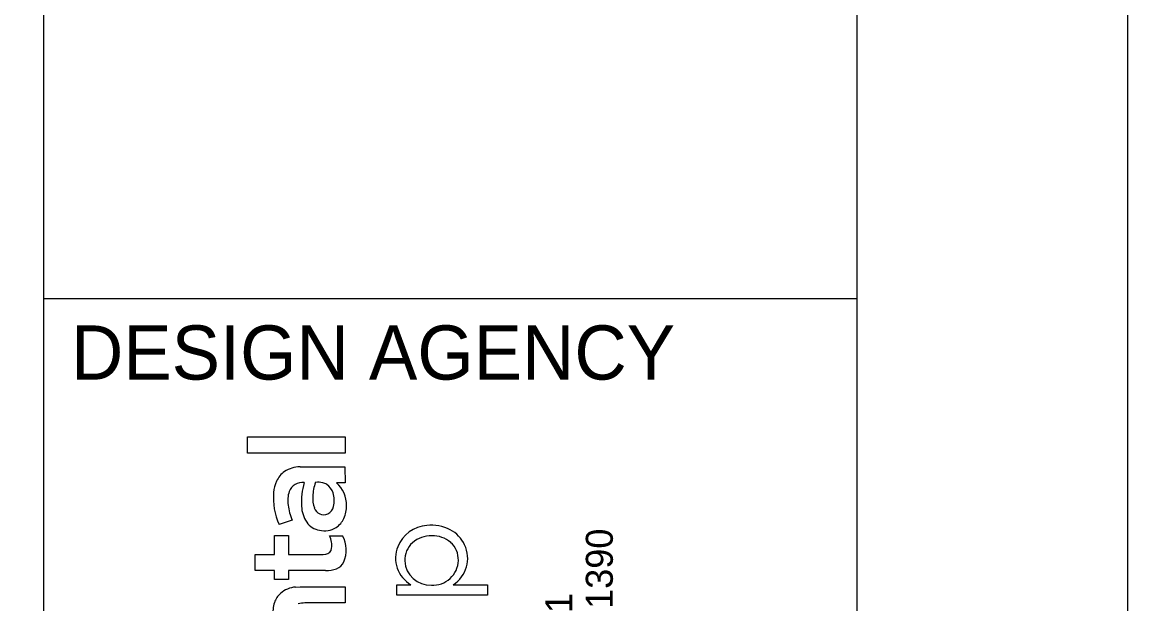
# Model space of a CAD drawing. Extents: x 0 to 34, y 0 to 22.
# Drawn here: x 31.96 to 34, y 4.436 to 5.51 of the extents above; entities that cross this region are included whole.
import ezdxf

# ---------------------------------------------------------------- set-up
doc = ezdxf.new("R2010")
doc.units = 0
for name, color, linetype in [('SH_Border', 7, 'Continuous'), ('SH_Cut_Line', 7, 'Continuous'), ('SH_Data', 7, 'Continuous')]:
    doc.layers.add(name, color=color, linetype=linetype)

msp = doc.modelspace()

# ---------------------------------------------------------------- linework, layer by layer
at = {"layer": 'SH_Border'}
for p, q in [((32, 0.5), (32, 21.5)), ((32, 5), (33.5, 5))]:
    msp.add_line(p, q, dxfattribs=at)
msp.add_lwpolyline([(1.5, 21.5), (33.5, 21.5), (33.5, 0.5), (1.5, 0.5)], close=True, dxfattribs=at)
at = {"layer": 'SH_Cut_Line'}
msp.add_lwpolyline([(0, 0), (34, 0), (34, 22), (0, 22)], close=True, dxfattribs=at)
at = {"layer": 'SH_Data'}
for p, q in [((32.3756, 4.7141), (32.3756, 4.744)), ((32.3756, 4.744), (32.5557, 4.744)), ((32.5557, 4.744), (32.5557, 4.7141)), ((32.5557, 4.7141), (32.3756, 4.7141)), ((32.4727, 4.689), (32.5555, 4.6892)), ((32.5555, 4.6892), (32.5557, 4.6596)), ((32.5557, 4.6596), (32.5397, 4.6596)), ((32.4582, 4.5904), (32.4343, 4.5823)), ((32.4254, 4.527), (32.4255, 4.5621)), ((32.4255, 4.5621), (32.4511, 4.5621)), ((32.4511, 4.5621), (32.4512, 4.527)), ((32.527, 4.5616), (32.5511, 4.5616)), ((32.3896, 4.4972), (32.3896, 4.527)), ((32.3896, 4.527), (32.4254, 4.527)), ((32.4512, 4.527), (32.515, 4.527)), ((32.515, 4.527), (32.52, 4.5275)), ((32.4254, 4.4972), (32.3896, 4.4972)), ((32.4254, 4.4807), (32.4254, 4.4972)), ((32.5197, 4.4972), (32.4511, 4.4972)), ((32.4511, 4.4972), (32.4511, 4.4807)), ((32.4511, 4.4807), (32.4254, 4.4807)), ((32.6515, 4.4521), (32.6515, 4.4711)), ((32.6515, 4.4711), (32.6771, 4.4711)), ((32.7549, 4.4713), (32.8186, 4.4711)), ((32.8186, 4.4711), (32.8184, 4.4521)), ((32.4644, 4.4669), (32.4729, 4.4673)), ((32.4729, 4.4673), (32.5557, 4.4673)), ((32.5557, 4.4673), (32.5557, 4.4375)), ((32.8184, 4.4521), (32.6515, 4.4521)), ((32.5557, 4.4375), (32.4814, 4.4375))]:
    msp.add_line(p, q, dxfattribs=at)
msp.add_lwpolyline([(32.3756, 4.7141), (32.3756, 4.744), (32.5557, 4.744), (32.5557, 4.7141)], close=True, dxfattribs=at)
for points in [[(32.4727, 4.689), (32.5555, 4.6892), (32.5557, 4.6596)], [(32.5557, 4.6596), (32.5397, 4.6596)], [(32.4582, 4.5904), (32.4343, 4.5823)], [(32.5197, 4.4972), (32.4511, 4.4972), (32.4511, 4.4807), (32.4254, 4.4807), (32.4254, 4.4972), (32.3896, 4.4972), (32.3896, 4.527), (32.4254, 4.527), (32.4255, 4.5621), (32.4511, 4.5621), (32.4512, 4.527), (32.515, 4.527), (32.52, 4.5275)], [(32.527, 4.5616), (32.5511, 4.5616)], [(32.7549, 4.4713), (32.8186, 4.4711), (32.8184, 4.4521), (32.6515, 4.4521)], [(32.6515, 4.4521), (32.6515, 4.4711), (32.6771, 4.4711)], [(32.4644, 4.4669), (32.4729, 4.4673), (32.5557, 4.4673), (32.5557, 4.4375), (32.4814, 4.4375)]]:
    msp.add_lwpolyline(points, dxfattribs=at)
for centre, radius, start, end in [((32.4685, 4.6447), 0.043, 124.537, 155.6594), ((32.4685, 4.6447), 0.043, 124.537, 155.6594), ((32.4745, 4.6326), 0.0565, 91.8942, 122.6317), ((32.4745, 4.6326), 0.0565, 91.8942, 122.6317), ((32.4882, 4.6361), 0.0646, 155.9764, 175.3149), ((32.4882, 4.6361), 0.0646, 155.9764, 175.3149), ((32.4753, 4.6356), 0.024, 119.4252, 161.6629), ((32.4753, 4.6356), 0.024, 119.4252, 161.6629), ((32.4779, 4.6278), 0.0321, 85.3802, 116.6222), ((32.4779, 4.6278), 0.0321, 85.3802, 116.6222), ((32.5879, 4.6251), 0.1129, 162.0821, 184.5285), ((32.5879, 4.6251), 0.1129, 162.0821, 184.5285), ((32.5801, 4.6313), 0.0841, 159.8366, 178.0362), ((32.5801, 4.6313), 0.0841, 159.8366, 178.0362), ((32.5051, 4.6074), 0.053, 79.6696, 94.2322), ((32.5051, 4.6074), 0.053, 79.6696, 94.2322), ((32.5089, 4.6364), 0.0238, 56.8913, 76.2149), ((32.5089, 4.6364), 0.0238, 56.8913, 76.2149), ((32.5052, 4.6318), 0.0297, 17.5984, 55.7282), ((32.5052, 4.6318), 0.0297, 17.5984, 55.7282), ((32.5055, 4.6191), 0.0529, 358.0746, 49.762), ((32.5055, 4.6191), 0.0529, 358.0746, 49.762), ((32.5364, 4.6308), 0.113, 174.6101, 205.3899), ((32.5364, 4.6308), 0.113, 174.6101, 205.3899), ((32.5076, 4.6265), 0.0576, 163.1369, 188.1675), ((32.5076, 4.6265), 0.0576, 163.1369, 188.1675), ((32.5466, 4.6303), 0.0506, 175.5903, 199.8857), ((32.5466, 4.6303), 0.0506, 175.5903, 199.8857), ((32.4916, 4.6264), 0.0443, 345.9408, 18.9919), ((32.4916, 4.6264), 0.0443, 345.9408, 18.9919), ((32.5473, 4.6297), 0.0973, 186.7598, 203.7981), ((32.5473, 4.6297), 0.0973, 186.7598, 203.7981), ((32.5328, 4.6187), 0.0575, 182.5676, 213.7144), ((32.5328, 4.6187), 0.0575, 182.5676, 213.7144), ((32.5164, 4.6189), 0.0184, 198.2844, 293.3081), ((32.5164, 4.6189), 0.0184, 198.2844, 293.3081), ((32.5152, 4.6199), 0.0199, 295.2883, 347.4639), ((32.5152, 4.6199), 0.0199, 295.2883, 347.4639), ((32.5019, 4.6168), 0.0566, 336.016, 0.5951), ((32.5019, 4.6168), 0.0566, 336.016, 0.5951), ((32.5175, 4.6097), 0.0394, 303.4436, 336.18), ((32.5175, 4.6097), 0.0394, 303.4436, 336.18), ((32.5149, 4.6078), 0.0366, 215.0668, 259.8133), ((32.5149, 4.6078), 0.0366, 215.0668, 259.8133), ((32.5175, 4.6131), 0.0423, 257.5256, 300.882), ((32.5175, 4.6131), 0.0423, 257.5256, 300.882), ((32.7108, 4.5182), 0.0624, 93.9866, 158.3119), ((32.7108, 4.5182), 0.0624, 93.9866, 158.3119), ((32.7156, 4.5065), 0.0746, 62.6889, 97.0135), ((32.7156, 4.5065), 0.0746, 62.6889, 97.0135), ((32.7212, 4.5191), 0.0608, 25.0657, 61.9602), ((32.7212, 4.5191), 0.0608, 25.0657, 61.9602), ((32.4863, 4.542), 0.0452, 10.1545, 25.723), ((32.4863, 4.542), 0.0452, 10.1545, 25.723), ((32.4957, 4.5436), 0.0356, 351.914, 10.2059), ((32.4957, 4.5436), 0.0356, 351.914, 10.2059), ((32.503, 4.5351), 0.0549, 336.589, 28.8991), ((32.503, 4.5351), 0.0549, 336.589, 28.8991), ((32.7138, 4.5102), 0.0513, 87.8965, 131.1812), ((32.7138, 4.5102), 0.0513, 87.8965, 131.1812), ((32.7175, 4.5102), 0.0513, 49.9089, 92.0363), ((32.7175, 4.5102), 0.0513, 49.9089, 92.0363), ((32.5184, 4.54), 0.0126, 277.6142, 353.7918), ((32.5184, 4.54), 0.0126, 277.6142, 353.7918), ((32.707, 4.5202), 0.0581, 158.656, 198.171), ((32.707, 4.5202), 0.0581, 158.656, 198.171), ((32.7092, 4.5167), 0.0434, 132.3289, 182.0949), ((32.7092, 4.5167), 0.0434, 132.3289, 182.0949), ((32.7215, 4.5173), 0.0433, 358.0487, 47.9447), ((32.7215, 4.5173), 0.0433, 358.0487, 47.9447), ((32.7245, 4.52), 0.0574, 301.9776, 25.6418), ((32.7245, 4.52), 0.0574, 301.9776, 25.6418), ((32.5291, 4.5261), 0.0275, 292.6889, 332.0598), ((32.5291, 4.5261), 0.0275, 292.6889, 332.0598), ((32.7135, 4.5181), 0.0478, 183.5974, 271.7045), ((32.7135, 4.5181), 0.0478, 183.5974, 271.7045), ((32.7172, 4.518), 0.0477, 267.3149, 357.4019), ((32.7172, 4.518), 0.0477, 267.3149, 357.4019), ((32.5209, 4.5486), 0.0514, 268.6727, 291.5235), ((32.5209, 4.5486), 0.0514, 268.6727, 291.5235), ((32.7103, 4.5243), 0.0627, 200.8399, 238.0162), ((32.7103, 4.5243), 0.0627, 200.8399, 238.0162), ((32.4635, 4.4255), 0.0402, 132.2238, 161.6823), ((32.4635, 4.4255), 0.0402, 132.2238, 161.6823), ((32.4687, 4.4172), 0.0499, 94.9706, 130.2248), ((32.4687, 4.4172), 0.0499, 94.9706, 130.2248), ((32.4787, 4.4211), 0.056, 162.274, 187.7917), ((32.4787, 4.4211), 0.056, 162.274, 187.7917), ((32.4811, 4.3915), 0.046, 89.6051, 105.3303), ((32.4811, 4.3915), 0.046, 89.6051, 105.3303)]:
    msp.add_arc(centre, radius, start, end, dxfattribs=at)

# ---------------------------------------------------------------- texts
msp.add_text('DESIGN AGENCY', height=0.1, dxfattribs=at).set_placement((32.05, 4.85))
for s, p in [('800.835.1390', (33.0497, 4.1671)), ('450 GRANT ST., AKRON, OH  44311', (32.9749, 3.3374))]:
    msp.add_text(s, height=0.049846, rotation=90, dxfattribs=at).set_placement(p)

doc.saveas('drawing.dxf')
